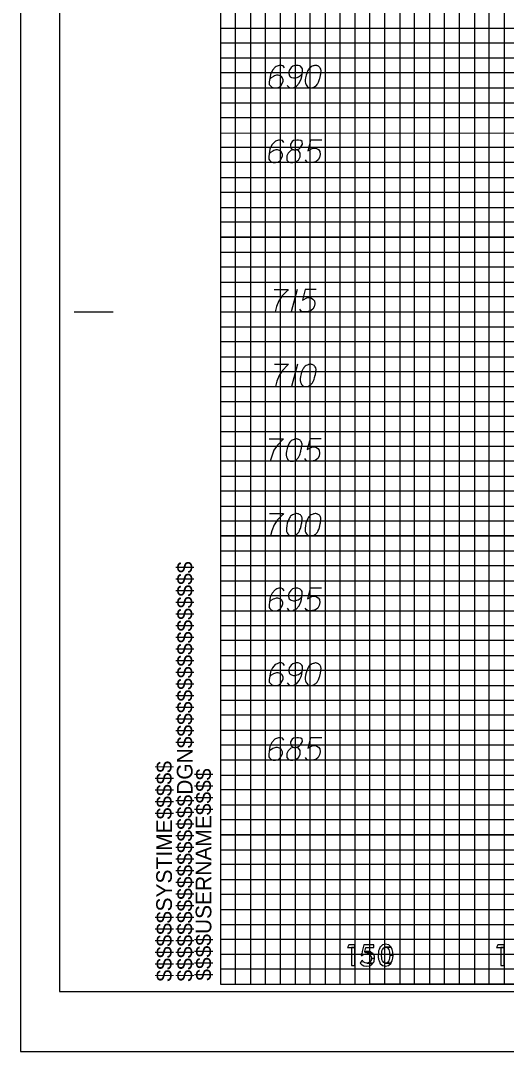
# Model space of a CAD drawing. Extents: x -13 to 323, y -5 to 1431.
# Drawn here: x -13.4 to 19.1, y 215.5 to 284.5 of the extents above; entities that cross this region are included whole.
import ezdxf

# ---------------------------------------------------------------- set-up
doc = ezdxf.new("R2010")
doc.units = 0
for name, color, linetype in [('Prop XS Elevation Labels', 7, 'Continuous'), ('Prop XS Offset Labels', 7, 'Continuous'), ('Sheet Cross Section CELL', 7, 'Continuous'), ('Sheet Cross Section Grid Major CELL', 7, 'Continuous'), ('Sheet Cross Section Grid Middle CELL', 7, 'Continuous'), ('Sheet Cross Section Grid Minor 1 CELL', 7, 'Continuous'), ('Sheet Cross Section Grid Minor 2 CELL', 7, 'Continuous'), ('Sheet Cutting Line CELL', 7, 'Continuous'), ('Sheet DOT Grid CELL', 7, 'Continuous'), ('Sheet Plot Border Inside CELL', 7, 'Continuous'), ('Sheet Plot Border Outside CELL', 7, 'Continuous')]:
    doc.layers.add(name, color=color, linetype=linetype)

msp = doc.modelspace()

# ---------------------------------------------------------------- linework, layer by layer
at = {"layer": 'Prop XS Elevation Labels'}
for p, q in [((5.124, 266.5), (4.723, 265)), ((5.142, 261.5), (4.74, 260))]:
    msp.add_line(p, q, dxfattribs=at)
for points in [[(4.28, 281.335), (4.185, 281.465), (4.079, 281.5), (3.914, 281.5), (3.795, 281.453), (3.725, 281.429), (3.666, 281.394), (3.477, 281.181), (3.347, 280.898), (3.311, 280.744), (3.264, 280.402), (3.264, 280.224), (3.311, 280.154), (3.406, 280.059), (3.441, 280.035), (3.559, 280), (3.713, 280), (3.831, 280.024), (3.914, 280.047), (4.032, 280.142), (4.15, 280.331), (4.185, 280.449), (4.185, 280.543), (4.126, 280.697), (4.079, 280.756), (3.996, 280.803), (3.854, 280.839), (3.748, 280.839), (3.618, 280.803), (3.536, 280.768), (3.394, 280.673), (3.323, 280.614), (3.288, 280.579)], [(4.468, 280.165), (4.563, 280.035), (4.669, 280), (4.835, 280), (4.953, 280.047), (5.024, 280.071), (5.083, 280.106), (5.272, 280.319), (5.401, 280.602), (5.437, 280.756), (5.484, 281.098), (5.484, 281.276), (5.437, 281.346), (5.342, 281.441), (5.307, 281.465), (5.189, 281.5), (5.036, 281.5), (4.917, 281.476), (4.835, 281.453), (4.717, 281.358), (4.598, 281.169), (4.563, 281.051), (4.563, 280.957), (4.622, 280.803), (4.669, 280.744), (4.752, 280.697), (4.894, 280.661), (5, 280.661), (5.13, 280.697), (5.213, 280.732), (5.354, 280.827), (5.425, 280.886), (5.461, 280.921)], [(6.382, 281.5), (6.358, 281.5), (6.287, 281.488), (6.24, 281.476), (6.204, 281.465), (6.145, 281.441), (6.074, 281.406), (6.015, 281.37), (5.956, 281.323), (5.921, 281.276), (5.885, 281.217), (5.85, 281.158), (5.815, 281.087), (5.791, 281.039), (5.767, 280.969), (5.732, 280.85), (5.697, 280.673), (5.673, 280.531), (5.673, 280.402), (5.685, 280.307), (5.732, 280.201), (5.767, 280.142), (5.827, 280.071), (5.897, 280.024), (5.933, 280.012), (6.004, 280), (6.063, 280), (6.157, 280.012), (6.24, 280.035), (6.299, 280.071), (6.382, 280.13), (6.417, 280.165), (6.464, 280.213), (6.5, 280.26), (6.523, 280.295), (6.547, 280.354), (6.559, 280.378), (6.582, 280.437), (6.606, 280.508), (6.63, 280.579), (6.642, 280.626), (6.653, 280.661), (6.665, 280.709), (6.689, 280.815), (6.701, 280.874), (6.712, 280.933), (6.724, 281.016), (6.736, 281.122), (6.736, 281.158), (6.724, 281.205), (6.712, 281.252), (6.677, 281.323), (6.642, 281.37), (6.606, 281.406), (6.559, 281.441), (6.512, 281.465), (6.476, 281.476), (6.441, 281.488), (6.382, 281.5)], [(4.238, 276.335), (4.144, 276.465), (4.038, 276.5), (3.872, 276.5), (3.754, 276.453), (3.683, 276.429), (3.624, 276.394), (3.435, 276.181), (3.305, 275.898), (3.27, 275.744), (3.223, 275.402), (3.223, 275.224), (3.27, 275.154), (3.364, 275.059), (3.4, 275.035), (3.518, 275), (3.671, 275), (3.79, 275.024), (3.872, 275.047), (3.99, 275.142), (4.108, 275.331), (4.144, 275.449), (4.144, 275.543), (4.085, 275.697), (4.038, 275.756), (3.955, 275.803), (3.813, 275.839), (3.707, 275.839), (3.577, 275.803), (3.494, 275.768), (3.352, 275.673), (3.282, 275.614), (3.246, 275.579)], [(4.899, 275.85), (5.065, 275.85), (5.112, 275.862), (5.254, 275.921), (5.36, 276.016), (5.478, 276.24), (5.466, 276.406), (5.384, 276.465), (5.218, 276.5), (5.1, 276.5), (4.876, 276.465), (4.805, 276.406), (4.687, 276.228), (4.675, 276.169), (4.699, 275.992), (4.746, 275.921), (4.899, 275.85), (4.711, 275.803), (4.533, 275.626), (4.439, 275.449), (4.427, 275.39), (4.439, 275.165), (4.545, 275.047), (4.687, 275), (4.829, 275), (5.053, 275.059), (5.218, 275.165), (5.325, 275.378), (5.337, 275.449), (5.325, 275.638), (5.23, 275.803), (5.065, 275.85)], [(6.777, 276.5), (6.033, 276.5), (5.844, 275.791), (6.187, 275.969), (6.388, 275.969), (6.553, 275.862), (6.648, 275.744), (6.671, 275.543), (6.636, 275.342), (6.541, 275.177), (6.376, 275.047), (6.092, 275), (5.88, 275), (5.773, 275.047), (5.679, 275.177)], [(3.589, 266.5), (4.533, 266.5), (4.474, 266.441), (4.132, 266.075), (3.896, 265.744), (3.754, 265.354), (3.659, 265)], [(6.411, 266.5), (5.667, 266.5), (5.478, 265.791), (5.821, 265.969), (6.022, 265.969), (6.187, 265.862), (6.282, 265.744), (6.305, 265.543), (6.27, 265.342), (6.175, 265.177), (6.01, 265.047), (5.726, 265), (5.514, 265), (5.408, 265.047), (5.313, 265.177)], [(3.606, 261.5), (4.551, 261.5), (4.492, 261.441), (4.149, 261.075), (3.913, 260.744), (3.772, 260.354), (3.677, 260)], [(6.039, 261.5), (6.016, 261.5), (5.945, 261.488), (5.898, 261.476), (5.862, 261.465), (5.803, 261.441), (5.732, 261.406), (5.673, 261.37), (5.614, 261.323), (5.579, 261.276), (5.543, 261.217), (5.508, 261.158), (5.472, 261.087), (5.449, 261.039), (5.425, 260.969), (5.39, 260.85), (5.354, 260.673), (5.331, 260.531), (5.331, 260.402), (5.343, 260.307), (5.39, 260.201), (5.425, 260.142), (5.484, 260.071), (5.555, 260.024), (5.591, 260.012), (5.661, 260), (5.72, 260), (5.815, 260.012), (5.898, 260.035), (5.957, 260.071), (6.039, 260.13), (6.075, 260.165), (6.122, 260.213), (6.157, 260.26), (6.181, 260.295), (6.205, 260.354), (6.217, 260.378), (6.24, 260.437), (6.264, 260.508), (6.287, 260.579), (6.299, 260.626), (6.311, 260.661), (6.323, 260.709), (6.347, 260.815), (6.358, 260.874), (6.37, 260.933), (6.382, 261.016), (6.394, 261.122), (6.394, 261.158), (6.382, 261.205), (6.37, 261.252), (6.335, 261.323), (6.299, 261.37), (6.264, 261.406), (6.217, 261.441), (6.169, 261.465), (6.134, 261.476), (6.098, 261.488), (6.039, 261.5)], [(3.258, 256.5), (4.203, 256.5), (4.144, 256.441), (3.801, 256.075), (3.565, 255.744), (3.423, 255.354), (3.329, 255)], [(5.1, 256.5), (5.077, 256.5), (5.006, 256.488), (4.959, 256.476), (4.923, 256.465), (4.864, 256.441), (4.793, 256.406), (4.734, 256.37), (4.675, 256.323), (4.64, 256.276), (4.604, 256.217), (4.569, 256.158), (4.534, 256.087), (4.51, 256.039), (4.486, 255.969), (4.451, 255.85), (4.415, 255.673), (4.392, 255.531), (4.392, 255.402), (4.404, 255.307), (4.451, 255.201), (4.486, 255.142), (4.545, 255.071), (4.616, 255.024), (4.652, 255.012), (4.723, 255), (4.781, 255), (4.876, 255.012), (4.959, 255.035), (5.018, 255.071), (5.1, 255.13), (5.136, 255.165), (5.183, 255.213), (5.219, 255.26), (5.242, 255.295), (5.266, 255.354), (5.278, 255.378), (5.301, 255.437), (5.325, 255.508), (5.349, 255.579), (5.36, 255.626), (5.372, 255.661), (5.384, 255.709), (5.408, 255.815), (5.419, 255.874), (5.431, 255.933), (5.443, 256.016), (5.455, 256.122), (5.455, 256.158), (5.443, 256.205), (5.431, 256.252), (5.396, 256.323), (5.36, 256.37), (5.325, 256.406), (5.278, 256.441), (5.23, 256.465), (5.195, 256.476), (5.16, 256.488), (5.1, 256.5)], [(6.742, 256.5), (5.998, 256.5), (5.809, 255.791), (6.152, 255.969), (6.352, 255.969), (6.518, 255.862), (6.612, 255.744), (6.636, 255.543), (6.6, 255.342), (6.506, 255.177), (6.341, 255.047), (6.057, 255), (5.845, 255), (5.738, 255.047), (5.644, 255.177)], [(3.276, 251.5), (4.22, 251.5), (4.161, 251.441), (3.819, 251.075), (3.583, 250.744), (3.441, 250.354), (3.346, 250)], [(5.118, 251.5), (5.094, 251.5), (5.024, 251.488), (4.977, 251.476), (4.941, 251.465), (4.882, 251.441), (4.811, 251.406), (4.752, 251.37), (4.693, 251.323), (4.658, 251.276), (4.622, 251.217), (4.587, 251.158), (4.551, 251.087), (4.528, 251.039), (4.504, 250.969), (4.469, 250.85), (4.433, 250.673), (4.409, 250.531), (4.409, 250.402), (4.421, 250.307), (4.469, 250.201), (4.504, 250.142), (4.563, 250.071), (4.634, 250.024), (4.669, 250.012), (4.74, 250), (4.799, 250), (4.894, 250.012), (4.977, 250.035), (5.036, 250.071), (5.118, 250.13), (5.154, 250.165), (5.201, 250.213), (5.236, 250.26), (5.26, 250.295), (5.283, 250.354), (5.295, 250.378), (5.319, 250.437), (5.342, 250.508), (5.366, 250.579), (5.378, 250.626), (5.39, 250.661), (5.402, 250.709), (5.425, 250.815), (5.437, 250.874), (5.449, 250.933), (5.461, 251.016), (5.473, 251.122), (5.473, 251.158), (5.461, 251.205), (5.449, 251.252), (5.413, 251.323), (5.378, 251.37), (5.342, 251.406), (5.295, 251.441), (5.248, 251.465), (5.213, 251.476), (5.177, 251.488), (5.118, 251.5)], [(6.37, 251.5), (6.346, 251.5), (6.276, 251.488), (6.228, 251.476), (6.193, 251.465), (6.134, 251.441), (6.063, 251.406), (6.004, 251.37), (5.945, 251.323), (5.909, 251.276), (5.874, 251.217), (5.838, 251.158), (5.803, 251.087), (5.779, 251.039), (5.756, 250.969), (5.721, 250.85), (5.685, 250.673), (5.661, 250.531), (5.661, 250.402), (5.673, 250.307), (5.721, 250.201), (5.756, 250.142), (5.815, 250.071), (5.886, 250.024), (5.921, 250.012), (5.992, 250), (6.051, 250), (6.146, 250.012), (6.228, 250.035), (6.287, 250.071), (6.37, 250.13), (6.406, 250.165), (6.453, 250.213), (6.488, 250.26), (6.512, 250.295), (6.535, 250.354), (6.547, 250.378), (6.571, 250.437), (6.594, 250.508), (6.618, 250.579), (6.63, 250.626), (6.642, 250.661), (6.653, 250.709), (6.677, 250.815), (6.689, 250.874), (6.701, 250.933), (6.713, 251.016), (6.724, 251.122), (6.724, 251.158), (6.713, 251.205), (6.701, 251.252), (6.665, 251.323), (6.63, 251.37), (6.594, 251.406), (6.547, 251.441), (6.5, 251.465), (6.464, 251.476), (6.429, 251.488), (6.37, 251.5)], [(4.262, 246.335), (4.168, 246.465), (4.061, 246.5), (3.896, 246.5), (3.778, 246.453), (3.707, 246.429), (3.648, 246.394), (3.459, 246.181), (3.329, 245.898), (3.294, 245.744), (3.246, 245.402), (3.246, 245.224), (3.294, 245.154), (3.388, 245.059), (3.423, 245.035), (3.542, 245), (3.695, 245), (3.813, 245.024), (3.896, 245.047), (4.014, 245.142), (4.132, 245.331), (4.168, 245.449), (4.168, 245.543), (4.109, 245.697), (4.061, 245.756), (3.979, 245.803), (3.837, 245.839), (3.73, 245.839), (3.601, 245.803), (3.518, 245.768), (3.376, 245.673), (3.305, 245.614), (3.27, 245.579)], [(4.451, 245.165), (4.545, 245.035), (4.652, 245), (4.817, 245), (4.935, 245.047), (5.006, 245.071), (5.065, 245.106), (5.254, 245.319), (5.384, 245.602), (5.419, 245.756), (5.467, 246.098), (5.467, 246.276), (5.419, 246.346), (5.325, 246.441), (5.289, 246.465), (5.171, 246.5), (5.018, 246.5), (4.9, 246.476), (4.817, 246.453), (4.699, 246.358), (4.581, 246.169), (4.545, 246.051), (4.545, 245.957), (4.604, 245.803), (4.652, 245.744), (4.734, 245.697), (4.876, 245.661), (4.982, 245.661), (5.112, 245.697), (5.195, 245.732), (5.337, 245.827), (5.408, 245.886), (5.443, 245.921)], [(6.754, 246.5), (6.01, 246.5), (5.821, 245.791), (6.163, 245.969), (6.364, 245.969), (6.529, 245.862), (6.624, 245.744), (6.647, 245.543), (6.612, 245.342), (6.517, 245.177), (6.352, 245.047), (6.069, 245), (5.856, 245), (5.75, 245.047), (5.655, 245.177)], [(4.28, 241.335), (4.185, 241.465), (4.079, 241.5), (3.914, 241.5), (3.795, 241.453), (3.725, 241.429), (3.666, 241.394), (3.477, 241.181), (3.347, 240.898), (3.311, 240.744), (3.264, 240.402), (3.264, 240.224), (3.311, 240.154), (3.406, 240.059), (3.441, 240.035), (3.559, 240), (3.713, 240), (3.831, 240.024), (3.914, 240.047), (4.032, 240.142), (4.15, 240.331), (4.185, 240.449), (4.185, 240.543), (4.126, 240.697), (4.079, 240.756), (3.996, 240.803), (3.854, 240.839), (3.748, 240.839), (3.618, 240.803), (3.536, 240.768), (3.394, 240.673), (3.323, 240.614), (3.288, 240.579)], [(4.468, 240.165), (4.563, 240.035), (4.669, 240), (4.835, 240), (4.953, 240.047), (5.024, 240.071), (5.083, 240.106), (5.272, 240.319), (5.401, 240.602), (5.437, 240.756), (5.484, 241.098), (5.484, 241.276), (5.437, 241.346), (5.342, 241.441), (5.307, 241.465), (5.189, 241.5), (5.036, 241.5), (4.917, 241.476), (4.835, 241.453), (4.717, 241.358), (4.598, 241.169), (4.563, 241.051), (4.563, 240.957), (4.622, 240.803), (4.669, 240.744), (4.752, 240.697), (4.894, 240.661), (5, 240.661), (5.13, 240.697), (5.213, 240.732), (5.354, 240.827), (5.425, 240.886), (5.461, 240.921)], [(6.382, 241.5), (6.358, 241.5), (6.287, 241.488), (6.24, 241.476), (6.204, 241.465), (6.145, 241.441), (6.074, 241.406), (6.015, 241.37), (5.956, 241.323), (5.921, 241.276), (5.885, 241.217), (5.85, 241.158), (5.815, 241.087), (5.791, 241.039), (5.767, 240.969), (5.732, 240.85), (5.697, 240.673), (5.673, 240.531), (5.673, 240.402), (5.685, 240.307), (5.732, 240.201), (5.767, 240.142), (5.827, 240.071), (5.897, 240.024), (5.933, 240.012), (6.004, 240), (6.063, 240), (6.157, 240.012), (6.24, 240.035), (6.299, 240.071), (6.382, 240.13), (6.417, 240.165), (6.464, 240.213), (6.5, 240.26), (6.523, 240.295), (6.547, 240.354), (6.559, 240.378), (6.582, 240.437), (6.606, 240.508), (6.63, 240.579), (6.642, 240.626), (6.653, 240.661), (6.665, 240.709), (6.689, 240.815), (6.701, 240.874), (6.712, 240.933), (6.724, 241.016), (6.736, 241.122), (6.736, 241.158), (6.724, 241.205), (6.712, 241.252), (6.677, 241.323), (6.642, 241.37), (6.606, 241.406), (6.559, 241.441), (6.512, 241.465), (6.476, 241.476), (6.441, 241.488), (6.382, 241.5)], [(4.238, 236.335), (4.144, 236.465), (4.038, 236.5), (3.872, 236.5), (3.754, 236.453), (3.683, 236.429), (3.624, 236.394), (3.435, 236.181), (3.305, 235.898), (3.27, 235.744), (3.223, 235.402), (3.223, 235.224), (3.27, 235.154), (3.364, 235.059), (3.4, 235.035), (3.518, 235), (3.671, 235), (3.79, 235.024), (3.872, 235.047), (3.99, 235.142), (4.108, 235.331), (4.144, 235.449), (4.144, 235.543), (4.085, 235.697), (4.038, 235.756), (3.955, 235.803), (3.813, 235.839), (3.707, 235.839), (3.577, 235.803), (3.494, 235.768), (3.352, 235.673), (3.282, 235.614), (3.246, 235.579)], [(4.899, 235.85), (5.065, 235.85), (5.112, 235.862), (5.254, 235.921), (5.36, 236.016), (5.478, 236.24), (5.466, 236.406), (5.384, 236.465), (5.218, 236.5), (5.1, 236.5), (4.876, 236.465), (4.805, 236.406), (4.687, 236.228), (4.675, 236.169), (4.699, 235.992), (4.746, 235.921), (4.899, 235.85), (4.711, 235.803), (4.533, 235.626), (4.439, 235.449), (4.427, 235.39), (4.439, 235.165), (4.545, 235.047), (4.687, 235), (4.829, 235), (5.053, 235.059), (5.218, 235.165), (5.325, 235.378), (5.337, 235.449), (5.325, 235.638), (5.23, 235.803), (5.065, 235.85)], [(6.777, 236.5), (6.033, 236.5), (5.844, 235.791), (6.187, 235.969), (6.388, 235.969), (6.553, 235.862), (6.648, 235.744), (6.671, 235.543), (6.636, 235.342), (6.541, 235.177), (6.376, 235.047), (6.092, 235), (5.88, 235), (5.773, 235.047), (5.679, 235.177)]]:
    msp.add_lwpolyline(points, dxfattribs=at)
at = {"layer": 'Prop XS Offset Labels'}
for points in [[(8.581, 222.641), (8.492, 222.459), (8.99, 222.459), (8.99, 222.641)], [(8.781, 222.459), (8.781, 221.25), (8.99, 221.25), (8.99, 222.459)], [(9.427, 221.94), (9.424, 221.928), (9.495, 221.928), (9.508, 221.94), (9.524, 221.954), (9.595, 221.997), (9.627, 222.007), (9.697, 222.029), (9.811, 222.035), (10.219, 222.035), (10.211, 222.05), (10.076, 222.145), (9.655, 222.145), (9.658, 222.158), (9.658, 222.158), (9.663, 222.178), (9.738, 222.456), (10.263, 222.456), (10.263, 222.641), (9.6, 222.641), (9.554, 222.456), (9.486, 222.178), (9.481, 222.158), (9.478, 222.145), (9.454, 222.05), (9.451, 222.035), (9.449, 222.029), (9.444, 222.007), (9.441, 221.997), (9.431, 221.954)], [(9.888, 222.192), (9.75, 222.178), (9.96, 222.178), (9.888, 222.192)], [(10.851, 221.255), (11.051, 221.214), (11.245, 221.255), (11.256, 221.257), (11.422, 221.409), (11.047, 221.409), (11.038, 221.411), (11.033, 221.413), (10.928, 221.442), (10.841, 221.555), (10.841, 221.556), (10.841, 221.556), (10.813, 221.657), (10.813, 221.659), (10.793, 221.732), (10.792, 221.736), (10.774, 221.939), (10.774, 221.941), (10.774, 221.943), (10.792, 222.145), (10.812, 222.222), (10.813, 222.224), (10.839, 222.322), (10.84, 222.325), (10.928, 222.44), (11.041, 222.469), (11.045, 222.47), (11.055, 222.473), (11.425, 222.473), (11.262, 222.622), (11.254, 222.624), (11.053, 222.668), (11.053, 222.668), (10.845, 222.624), (10.843, 222.622), (10.681, 222.473), (10.678, 222.47), (10.678, 222.469), (10.665, 222.44), (10.618, 222.325), (10.617, 222.322), (10.577, 222.224), (10.576, 222.222), (10.568, 222.145), (10.547, 221.943), (10.547, 221.941), (10.547, 221.939), (10.567, 221.736), (10.568, 221.732), (10.575, 221.659), (10.575, 221.657), (10.616, 221.556), (10.617, 221.555), (10.663, 221.442), (10.675, 221.413), (10.676, 221.411), (10.679, 221.409), (10.848, 221.257)], [(11.312, 222.145), (11.328, 221.943), (11.555, 221.943), (11.536, 222.145), (11.528, 222.222), (11.527, 222.224), (11.527, 222.224), (11.488, 222.322), (11.488, 222.322), (11.487, 222.325), (11.441, 222.44), (11.44, 222.44), (11.429, 222.469), (11.428, 222.47), (11.425, 222.473), (11.055, 222.473), (11.065, 222.47), (11.068, 222.469), (11.175, 222.44), (11.262, 222.325), (11.265, 222.322), (11.291, 222.224), (11.291, 222.222)], [(18.581, 222.641), (18.492, 222.459), (18.99, 222.459), (18.99, 222.641)], [(18.781, 222.459), (18.781, 221.25), (18.99, 221.25), (18.99, 222.459)], [(9.626, 221.233), (9.762, 221.214), (9.959, 221.233), (9.968, 221.237), (10.091, 221.297), (10.091, 221.297), (10.141, 221.321), (10.185, 221.375), (10.204, 221.399), (9.793, 221.399), (9.683, 221.418), (9.682, 221.419), (9.679, 221.42), (9.596, 221.466), (9.586, 221.477), (9.58, 221.483), (9.58, 221.483), (9.529, 221.535), (9.497, 221.585), (9.497, 221.585), (9.451, 221.535), (9.404, 221.483), (9.399, 221.477), (9.39, 221.466), (9.348, 221.42), (9.347, 221.419), (9.348, 221.418), (9.363, 221.399), (9.382, 221.375), (9.445, 221.321), (9.474, 221.297), (9.598, 221.237)], [(9.424, 221.928), (9.482, 221.916), (9.495, 221.928)], [(9.692, 222.158), (9.655, 222.145), (10.076, 222.145), (10.058, 222.158), (9.961, 222.178), (9.75, 222.178)], [(9.9, 221.418), (9.793, 221.399), (10.204, 221.399), (10.22, 221.418), (10.221, 221.419), (10.222, 221.42), (10.222, 221.42), (10.259, 221.466), (10.268, 221.477), (10.27, 221.483), (10.284, 221.535), (10.299, 221.59), (10.322, 221.674), (10.318, 221.721), (10.105, 221.721), (10.097, 221.674), (10.082, 221.59), (10.047, 221.535), (10.014, 221.483), (10.004, 221.477), (9.987, 221.466), (9.913, 221.42), (9.905, 221.419)], [(10.083, 221.841), (10.105, 221.721), (10.318, 221.721), (10.307, 221.841), (10.307, 221.841), (10.303, 221.881), (10.284, 221.916), (10.278, 221.928), (10.271, 221.94), (10.263, 221.954), (10.24, 221.997), (10.235, 222.007), (10.223, 222.029), (10.219, 222.035), (9.811, 222.035), (9.838, 222.029), (9.928, 222.007), (9.943, 221.997), (10.003, 221.954), (10.024, 221.94), (10.031, 221.928), (10.038, 221.916), (10.059, 221.881)], [(11.058, 221.411), (11.047, 221.409), (11.422, 221.409), (11.425, 221.411), (11.426, 221.413), (11.438, 221.442), (11.485, 221.555), (11.485, 221.556), (11.527, 221.657), (11.528, 221.659), (11.535, 221.732), (11.535, 221.736), (11.555, 221.939), (11.556, 221.941), (11.555, 221.943), (11.328, 221.943), (11.328, 221.941), (11.328, 221.939), (11.312, 221.736), (11.312, 221.732), (11.292, 221.659), (11.291, 221.657), (11.264, 221.556), (11.263, 221.555), (11.175, 221.442), (11.063, 221.413)]]:
    msp.add_lwpolyline(points, close=True, dxfattribs=at)
at = {"layer": 'Sheet Cross Section CELL'}
for p, q in [((-9.8, 265), (-7.3, 265)), ((-9.7, 265), (-7.2, 265)), ((0, 220), (0, 220)), ((0, 220), (0, 220)), ((0, 220), (0, 220)), ((0, 220), (0, 220)), ((0, 220), (0, 220)), ((0, 220), (0, 220)), ((0, 220), (0, 220))]:
    msp.add_line(p, q, dxfattribs=at)
msp.add_lwpolyline([(320, 430), (0, 430), (0, 220), (320, 220)], close=True, dxfattribs=at)
at = {"layer": 'Sheet Cross Section Grid Major CELL'}
for p, q in [((10, 220), (10, 430)), ((20, 220), (10, 220))]:
    msp.add_line(p, q, dxfattribs=at)
for points in [[(0, 280), (320, 280), (320, 270), (0, 270)], [(0, 260), (320, 260), (320, 250), (0, 250)], [(0, 240), (320, 240), (320, 230), (0, 230)]]:
    msp.add_lwpolyline(points, dxfattribs=at)
at = {"layer": 'Sheet Cross Section Grid Middle CELL'}
for points in [[(5, 430), (5, 220), (15, 220), (15, 430)], [(0, 265), (320, 265), (320, 275), (0, 275)], [(0, 245), (320, 245), (320, 255), (0, 255)], [(0, 225), (320, 225), (320, 235), (0, 235)]]:
    msp.add_lwpolyline(points, dxfattribs=at)
at = {"layer": 'Sheet Cross Section Grid Minor 1 CELL'}
for points in [[(0, 284), (320, 284), (320, 283), (0, 283)], [(0, 282), (320, 282), (320, 281), (0, 281)], [(0, 279), (320, 279), (320, 278), (0, 278)], [(0, 276.99), (320.07, 276.91), (320, 276), (0, 276)], [(0, 274), (320, 274), (320, 273), (0, 273)], [(0, 272), (320, 272), (320, 271), (0, 271)], [(0, 269), (320, 269), (320, 268), (0, 268)], [(0, 267), (320, 267), (320, 266), (0, 266)], [(0, 264), (320, 264), (320, 263), (0, 263)], [(0, 262), (320, 262), (320, 261), (0, 261)], [(0, 259), (320, 259), (320, 258), (0, 258)], [(0, 257), (320, 257), (320, 256), (0, 256)], [(0, 254), (320, 254), (320, 253), (0, 253)], [(0, 252), (320, 252), (320, 251), (0, 251)], [(0, 249), (320, 249), (320, 248), (0, 248)], [(0, 247), (320, 247), (320, 246), (0, 246)], [(0, 244), (320, 244), (320, 243), (0, 243)], [(0, 242), (320, 242), (320, 241), (0, 241)], [(0, 239), (320, 239), (320, 238), (0, 238)], [(0, 237), (320, 237), (320, 236), (0, 236)], [(0, 234), (320, 234), (320, 233), (0, 233)], [(0, 232), (320, 232), (320, 231), (0, 231)], [(0, 229), (320, 229), (320, 228), (0, 228)], [(0, 227), (320, 227), (320, 226), (0, 226)], [(0, 224), (320, 224), (320, 223), (0, 223)], [(0, 222), (320, 222), (320, 221), (0, 221)]]:
    msp.add_lwpolyline(points, dxfattribs=at)
at = {"layer": 'Sheet Cross Section Grid Minor 2 CELL'}
for points in [[(0, 220), (1, 220), (1, 430), (2, 430), (2, 220)], [(2, 220), (3, 220), (3, 430), (4, 430), (4, 220)], [(5, 220), (6, 220), (6, 430), (7, 430), (7, 220)], [(7, 220), (8, 220), (8, 430), (9, 430), (9, 220)], [(10, 220), (11, 220), (11, 430), (12, 430), (12, 220)], [(12, 220), (13, 220), (13, 430), (14, 430), (14, 220)], [(15, 220), (16, 220), (16, 430), (17, 430), (17, 220)], [(17, 220), (18, 220), (18, 430), (19, 430), (19, 220)]]:
    msp.add_lwpolyline(points, dxfattribs=at)
at = {"layer": 'Sheet Cutting Line CELL'}
for p, q in [((-13.4, 434.5), (-13.4, 215.5)), ((-13.4, 215.5), (323.3, 215.5))]:
    msp.add_line(p, q, dxfattribs=at)
at = {"layer": 'Sheet DOT Grid CELL'}
for p, q in [((10, 220), (10, 430)), ((0, 280), (320, 280)), ((0, 270), (320, 270)), ((0, 260), (320, 260)), ((0, 250), (320, 250)), ((0, 240), (320, 240)), ((0, 230), (320, 230))]:
    msp.add_line(p, q, dxfattribs=at)
at = {"layer": 'Sheet Plot Border Inside CELL'}
msp.add_lwpolyline([(-10.8, 219.5), (322.4, 219.5), (322.4, 430.5), (-10.8, 430.5)], close=True, dxfattribs=at)
at = {"layer": 'Sheet Plot Border Outside CELL'}
msp.add_lwpolyline([(-13.4, 215.5), (323.3, 215.5), (323.3, 434.5), (-13.4, 434.5)], close=True, dxfattribs=at)

# ---------------------------------------------------------------- texts
at = {"layer": 'Sheet Cross Section CELL'}
for s, p in [('$$$$$$$$$$$$$$$$DGN$$$$$$$$$$$$$$$$', (-1.88, 220.18)), ('$$$$$$SYSTIME$$$$$', (-3.26, 220.18)), ('$$$$USERNAME$$$$', (-0.62, 220.23))]:
    msp.add_text(s, height=1.05, rotation=90, dxfattribs=at).set_placement(p)

doc.saveas('drawing.dxf')
